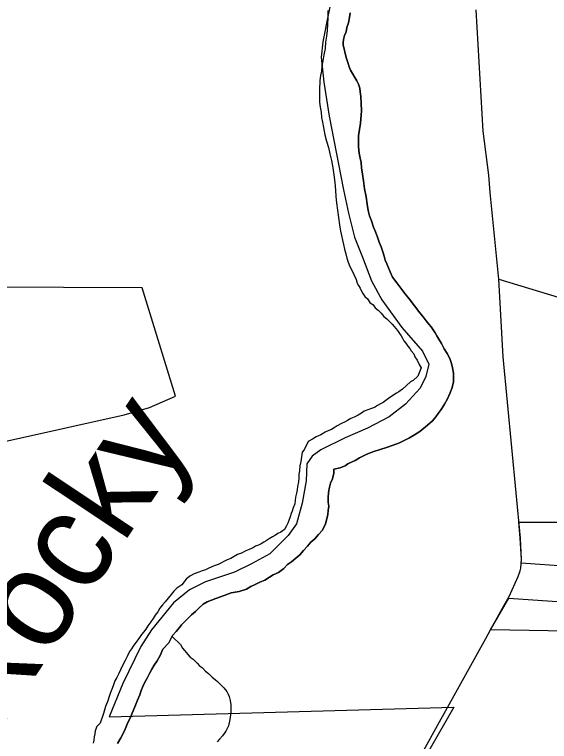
# Model space of a CAD drawing. Extents: x 2010165 to 2382125, y 1060529 to 1407316.
# Drawn here: x 2133800 to 2136008, y 1232184 to 1235186 of the extents above; entities that cross this region are included whole.
import ezdxf

# ---------------------------------------------------------------- set-up
doc = ezdxf.new("R2010")
doc.units = 0
for name, color, linetype in [('GM_X_City_Street', 7, 'Continuous'), ('GM_X_Corporation', 7, 'Continuous'), ('GM_X_County_Road', 7, 'Continuous'), ('GM_X_Major_River', 7, 'Continuous'), ('GM_X_Major_River_Text', 7, 'Continuous'), ('GM_X_Minor_River', 7, 'Continuous')]:
    doc.layers.add(name, color=color, linetype=linetype)

msp = doc.modelspace()

# ---------------------------------------------------------------- linework, layer by layer
at = {"layer": 'GM_X_City_Street'}
msp.add_lwpolyline([(2134256.4, 1229179.8), (2134217.3, 1230093.2), (2134232.4, 1230413.1), (2134251.3, 1230729.2), (2134250, 1230896), (2134276.8, 1231168.9), (2134371.9, 1231445.9), (2134414, 1231531.8), (2134446.8, 1231590.3), (2134486.2, 1231614), (2134514.5, 1231617.7), (2134918.3, 1231605.8), (2135099.6, 1231604.1), (2135244.1, 1231759), (2135312.9, 1231864.6), (2135445.4, 1232068.5), (2135560.9, 1232277.3), (2135566.6, 1232287.6)], dxfattribs=at)
at = {"layer": 'GM_X_Corporation'}
for points in [[(2130665.6, 1232672.5), (2131903.1, 1232704.3), (2131906.6, 1232844.7), (2132365.2, 1232836.8), (2132374.9, 1233391.5), (2133620.9, 1233404.8), (2133665.8, 1233408.5), (2133770.5, 1233426), (2134251.8, 1233533.2), (2134304.2, 1233548.1), (2134356.5, 1233563.1), (2134463.7, 1233610.5), (2134327.1, 1234057.3), (2132374.5, 1234066.3), (2132374.1, 1235700.8)], [(2135154.7, 1235473.1), (2135093.8, 1235177.9), (2135072.1, 1235073.6), (2135066.4, 1235009.3), (2135076.8, 1234907.1), (2135099.4, 1234766.8), (2135158.6, 1234462.3), (2135179, 1234366.1), (2135203.5, 1234265.9), (2135235.8, 1234183.9), (2135274.2, 1234085.8), (2135316.6, 1234007.7), (2135399.2, 1233893.8), (2135483.6, 1233795.9), (2135509.9, 1233741.9), (2135498.1, 1233691.7), (2135474.2, 1233643.5), (2135414.4, 1233577), (2135346.5, 1233524.5), (2135256.6, 1233478), (2135164.6, 1233437.5), (2135064.7, 1233388.9), (2135028.7, 1233362.6), (2135006.8, 1233330.4), (2135003.1, 1233260.2), (2134987.4, 1233167.9), (2134963.7, 1233083.5), (2134929.9, 1233035.3), (2134854.1, 1232958.7), (2134778.1, 1232918.2), (2134708.2, 1232883.8), (2134588.2, 1232843.1), (2134522.2, 1232810.7), (2134456.3, 1232756.3), (2134364.6, 1232645.5), (2134320.8, 1232577.2), (2134247.3, 1232424.4), (2134189.8, 1232285.7), (2135613.5, 1232326.5), (2135412.6, 1231974.5)], [(2136086.2, 1232907.1), (2135891.6, 1232920.2), (2135892.6, 1232935.4), (2135888, 1233024), (2135881.7, 1233090.1), (2136401.5, 1233090.1)], [(2139105.1, 1232587.1), (2135765.5, 1232645.4), (2135840.1, 1232775.5), (2136059.6, 1232760.8)]]:
    msp.add_lwpolyline(points, dxfattribs=at)
at = {"layer": 'GM_X_County_Road'}
for points in [[(2135889.6, 1232994), (2135888.1, 1233024), (2135816.7, 1233771.8), (2135799.8, 1234093.1), (2135763.7, 1234450.9), (2135758.5, 1234522.7), (2135735.2, 1234704.1), (2135705.7, 1235205.1)], [(2135799.8, 1234093.1), (2136211.7, 1233968.5), (2136363.9, 1233924), (2136372.3, 1233921.9)], [(2132404, 1233383.6), (2132621, 1233388.5), (2132832.9, 1233396), (2133473.8, 1233396), (2133576, 1233401), (2133620.9, 1233404.8), (2133665.8, 1233408.5), (2133770.5, 1233425.9), (2134251.8, 1233533.2), (2134304.2, 1233548.2), (2134356.5, 1233563.1), (2134463.7, 1233610.5)], [(2135887.2, 1232889.6), (2135890.3, 1232899.8), (2135892.6, 1232935.4), (2135889.6, 1232994)], [(2135821.9, 1232746.6), (2135841.9, 1232782.4), (2135879.7, 1232864.9), (2135887.2, 1232889.6)], [(2135745.2, 1232609), (2135765.4, 1232645.3), (2135821.9, 1232746.6)], [(2135566.6, 1232287.6), (2135745.2, 1232609)]]:
    msp.add_lwpolyline(points, dxfattribs=at)
at = {"layer": 'GM_X_Major_River'}
for points in [[(2135093.8, 1235202.7), (2135093.9, 1235170.6), (2135092, 1235146.5), (2135090.1, 1235120.4), (2135088.1, 1235096.3), (2135084.2, 1235072.2), (2135082.3, 1235046.1), (2135076.3, 1235020), (2135072.4, 1234993.9), (2135068.5, 1234973.9), (2135066.5, 1234951.8), (2135062.6, 1234933.7), (2135060.7, 1234913.6), (2135060.7, 1234899.6)], [(2135093.8, 1235202.7), (2135093.9, 1235170.6), (2135092, 1235146.5), (2135090.1, 1235120.4), (2135088.1, 1235096.3), (2135084.2, 1235072.2), (2135082.3, 1235046.1), (2135076.3, 1235020), (2135072.4, 1234993.9), (2135068.5, 1234973.9), (2135066.5, 1234951.8), (2135062.6, 1234933.7), (2135060.7, 1234913.6), (2135060.7, 1234899.6)], [(2135186.1, 1235193), (2135182.2, 1235172.9), (2135178.2, 1235150.8), (2135172.3, 1235132.7), (2135168.3, 1235114.6), (2135162.4, 1235098.6), (2135158.4, 1235082.5), (2135156.4, 1235070.4), (2135156.5, 1235060.4), (2135168.7, 1235008.3), (2135172.7, 1234996.3), (2135176.8, 1234984.2), (2135180.9, 1234970.2), (2135186.9, 1234956.2), (2135195, 1234942.1), (2135205.1, 1234926.1), (2135213.2, 1234912.1), (2135219.2, 1234898.1), (2135225.3, 1234882.1), (2135227.4, 1234866), (2135229.4, 1234847.9), (2135231.5, 1234819.9), (2135231.7, 1234787.8), (2135227.8, 1234737.6), (2135223.9, 1234711.5), (2135220, 1234685.4), (2135220.1, 1234661.3), (2135220.1, 1234639.2), (2135222.2, 1234613.1), (2135226.3, 1234593.1), (2135230.4, 1234575.1), (2135232.5, 1234553), (2135236.6, 1234526.9), (2135240.7, 1234498.8), (2135244.8, 1234466.7), (2135250.9, 1234432.6), (2135255.1, 1234402.6), (2135259.2, 1234376.5), (2135265.2, 1234354.4), (2135273.3, 1234334.4), (2135281.5, 1234308.3), (2135289.6, 1234288.3), (2135297.7, 1234266.2), (2135305.8, 1234246.2), (2135313.9, 1234226.1), (2135319.9, 1234206.1), (2135326, 1234188.1), (2135330.1, 1234172), (2135336.2, 1234156), (2135344.2, 1234140), (2135350.3, 1234123.9), (2135360.4, 1234101.9), (2135378.6, 1234077.9), (2135394.7, 1234055.8), (2135410.8, 1234033.8), (2135429, 1234011.8), (2135473.3, 1233953.8), (2135487.4, 1233937.7), (2135499.5, 1233921.7), (2135509.6, 1233907.7), (2135519.7, 1233895.7), (2135527.7, 1233883.7), (2135535.8, 1233871.7), (2135543.9, 1233859.7), (2135551.9, 1233845.6), (2135562, 1233827.6), (2135574.1, 1233805.6), (2135586.3, 1233785.6), (2135596.4, 1233765.5), (2135604.5, 1233745.5), (2135608.5, 1233727.4), (2135612.6, 1233705.4), (2135612.7, 1233683.3), (2135612.7, 1233669.2), (2135608.8, 1233657.2), (2135604.8, 1233641.1), (2135596.9, 1233621), (2135586.9, 1233598.9), (2135574.9, 1233576.8), (2135561, 1233554.7), (2135549, 1233538.6), (2135539, 1233524.5), (2135525, 1233508.4), (2135505, 1233490.3), (2135473, 1233464.1), (2135451, 1233450), (2135430.9, 1233437.9), (2135410.9, 1233427.8), (2135388.9, 1233417.7), (2135362.8, 1233407.6), (2135334.8, 1233397.5), (2135308.7, 1233389.4), (2135282.6, 1233381.3), (2135260.6, 1233373.2), (2135246.6, 1233367.1)], [(2135246.6, 1233367.1), (2135260.6, 1233373.2), (2135282.6, 1233381.3), (2135308.7, 1233389.4), (2135334.8, 1233397.5), (2135362.8, 1233407.6), (2135388.9, 1233417.7), (2135410.9, 1233427.8), (2135430.9, 1233437.9), (2135451, 1233450), (2135473, 1233464.1), (2135505, 1233490.3), (2135525, 1233508.4), (2135539, 1233524.5), (2135549, 1233538.6), (2135561, 1233554.7), (2135574.9, 1233576.8), (2135586.9, 1233598.9), (2135596.9, 1233621), (2135604.8, 1233641.1), (2135608.8, 1233657.2), (2135612.7, 1233669.2), (2135612.7, 1233683.3), (2135612.6, 1233705.4), (2135608.5, 1233727.4), (2135604.5, 1233745.5), (2135596.4, 1233765.5), (2135586.3, 1233785.6), (2135574.1, 1233805.6), (2135562, 1233827.6), (2135551.9, 1233845.6), (2135543.9, 1233859.7), (2135535.8, 1233871.7), (2135527.7, 1233883.7), (2135519.7, 1233895.7), (2135509.6, 1233907.7), (2135499.5, 1233921.7), (2135487.4, 1233937.7), (2135473.3, 1233953.8), (2135429, 1234011.8), (2135410.8, 1234033.8), (2135394.7, 1234055.8), (2135378.6, 1234077.9), (2135360.4, 1234101.9), (2135350.3, 1234123.9), (2135344.2, 1234140), (2135336.2, 1234156), (2135330.1, 1234172), (2135326, 1234188.1), (2135319.9, 1234206.1), (2135313.9, 1234226.1), (2135305.8, 1234246.2), (2135297.7, 1234266.2), (2135289.6, 1234288.3), (2135281.5, 1234308.3), (2135273.3, 1234334.4), (2135265.2, 1234354.4), (2135259.2, 1234376.5), (2135255.1, 1234402.6), (2135250.9, 1234432.6), (2135244.8, 1234466.7), (2135240.7, 1234498.8), (2135236.6, 1234526.9), (2135232.5, 1234553), (2135230.4, 1234575.1), (2135226.3, 1234593.1), (2135222.2, 1234613.1), (2135220.1, 1234639.2), (2135220.1, 1234661.3), (2135220, 1234685.4), (2135223.9, 1234711.5), (2135227.8, 1234737.6), (2135231.7, 1234787.8), (2135231.5, 1234819.9), (2135229.4, 1234847.9), (2135227.4, 1234866), (2135225.3, 1234882.1), (2135219.2, 1234898.1), (2135213.2, 1234912.1), (2135205.1, 1234926.1), (2135195, 1234942.1), (2135186.9, 1234956.2), (2135180.9, 1234970.2), (2135176.8, 1234984.2), (2135172.7, 1234996.3), (2135168.7, 1235008.3), (2135156.5, 1235060.4), (2135156.4, 1235070.4), (2135158.4, 1235082.5), (2135162.4, 1235098.6), (2135168.3, 1235114.6), (2135172.3, 1235132.7), (2135178.2, 1235150.8), (2135182.2, 1235172.9), (2135186.1, 1235193)], [(2135060.7, 1234899.6), (2135058.7, 1234887.5), (2135058.8, 1234873.5), (2135058.8, 1234859.4), (2135058.9, 1234843.4), (2135059, 1234823.3), (2135061, 1234803.3), (2135065.1, 1234783.2), (2135067.2, 1234761.1), (2135071.3, 1234741.1), (2135075.4, 1234719), (2135081.5, 1234688.9), (2135087.6, 1234662.9), (2135095.7, 1234636.8), (2135101.8, 1234610.8), (2135107.9, 1234582.7), (2135114.1, 1234552.6), (2135118.2, 1234524.5), (2135122.3, 1234492.4), (2135124.4, 1234460.3), (2135126.5, 1234434.2), (2135128.6, 1234408.2), (2135132.7, 1234378.1), (2135136.9, 1234348), (2135141, 1234317.9), (2135145.1, 1234291.8), (2135149.1, 1234273.8), (2135153.2, 1234253.7), (2135157.3, 1234235.7), (2135161.4, 1234217.6), (2135167.5, 1234197.6), (2135171.5, 1234179.6), (2135177.6, 1234163.5), (2135183.7, 1234145.5), (2135193.8, 1234127.4), (2135210, 1234091.4), (2135214, 1234077.3), (2135220.1, 1234067.3), (2135226.1, 1234055.3), (2135232.2, 1234043.3), (2135238.3, 1234033.3), (2135246.3, 1234021.3), (2135256.4, 1234011.3), (2135266.5, 1233997.2), (2135280.6, 1233987.2), (2135288.6, 1233975.2), (2135300.7, 1233965.2), (2135312.8, 1233953.2), (2135324.9, 1233939.2), (2135336.9, 1233929.2), (2135349, 1233917.2), (2135359.1, 1233907.2), (2135367.2, 1233897.2), (2135381.3, 1233881.2), (2135389.3, 1233869.2), (2135395.4, 1233859.2), (2135401.4, 1233849.2), (2135407.5, 1233839.2), (2135415.5, 1233829.2), (2135423.6, 1233817.1), (2135431.7, 1233807.1), (2135437.7, 1233797.1), (2135447.8, 1233785.1), (2135451.9, 1233773.1), (2135461.9, 1233759.1), (2135470, 1233741), (2135478.1, 1233727), (2135464.2, 1233692.9), (2135446.2, 1233674.7), (2135434.2, 1233668.7), (2135402.2, 1233638.5), (2135386.1, 1233628.4), (2135376.1, 1233622.3), (2135362.1, 1233612.3), (2135344.1, 1233600.2), (2135332.1, 1233592.1), (2135322.1, 1233584.1), (2135310.1, 1233578), (2135298, 1233571.9), (2135286, 1233563.9), (2135274, 1233559.8), (2135258, 1233553.8), (2135243.9, 1233547.7), (2135231.9, 1233539.6), (2135217.9, 1233531.6), (2135201.9, 1233523.5), (2135187.9, 1233517.4), (2135173.8, 1233509.3), (2135161.8, 1233503.3), (2135149.8, 1233497.2), (2135131.8, 1233487.1), (2135119.8, 1233479.1), (2135107.8, 1233473), (2135097.7, 1233469), (2135081.7, 1233460.9), (2135063.7, 1233450.8), (2135045.6, 1233442.7), (2135029.6, 1233432.6), (2135011.6, 1233422.5), (2134995.7, 1233388.4), (2134987.7, 1233378.3)], [(2135060.7, 1234899.6), (2135058.7, 1234887.5), (2135058.8, 1234873.5), (2135058.8, 1234859.4), (2135058.9, 1234843.4), (2135059, 1234823.3), (2135061, 1234803.3), (2135065.1, 1234783.2), (2135067.2, 1234761.1), (2135071.3, 1234741.1), (2135075.4, 1234719), (2135081.5, 1234688.9), (2135087.6, 1234662.9), (2135095.7, 1234636.8), (2135101.8, 1234610.8), (2135107.9, 1234582.7), (2135114.1, 1234552.6), (2135118.2, 1234524.5), (2135122.3, 1234492.4), (2135124.4, 1234460.3), (2135126.5, 1234434.2), (2135128.6, 1234408.2), (2135132.7, 1234378.1), (2135136.9, 1234348), (2135141, 1234317.9), (2135145.1, 1234291.8), (2135149.1, 1234273.8), (2135153.2, 1234253.7), (2135157.3, 1234235.7), (2135161.4, 1234217.6), (2135167.5, 1234197.6), (2135171.5, 1234179.6), (2135177.6, 1234163.5), (2135183.7, 1234145.5), (2135193.8, 1234127.4), (2135210, 1234091.4), (2135214, 1234077.3), (2135220.1, 1234067.3), (2135226.1, 1234055.3), (2135232.2, 1234043.3), (2135238.3, 1234033.3), (2135246.3, 1234021.3), (2135256.4, 1234011.3), (2135266.5, 1233997.2), (2135280.6, 1233987.2), (2135288.6, 1233975.2), (2135300.7, 1233965.2), (2135312.8, 1233953.2), (2135324.9, 1233939.2), (2135336.9, 1233929.2), (2135349, 1233917.2), (2135359.1, 1233907.2), (2135367.2, 1233897.2), (2135381.3, 1233881.2), (2135389.3, 1233869.2), (2135395.4, 1233859.2), (2135401.4, 1233849.2), (2135407.5, 1233839.2), (2135415.5, 1233829.2), (2135423.6, 1233817.1), (2135431.7, 1233807.1), (2135437.7, 1233797.1), (2135447.8, 1233785.1), (2135451.9, 1233773.1), (2135461.9, 1233759.1), (2135470, 1233741), (2135478.1, 1233727), (2135464.2, 1233692.9), (2135446.2, 1233674.7), (2135434.2, 1233668.7), (2135402.2, 1233638.5), (2135386.1, 1233628.4), (2135376.1, 1233622.3), (2135362.1, 1233612.3), (2135344.1, 1233600.2), (2135332.1, 1233592.1), (2135322.1, 1233584.1), (2135310.1, 1233578), (2135298, 1233571.9), (2135286, 1233563.9), (2135274, 1233559.8), (2135258, 1233553.8), (2135243.9, 1233547.7), (2135231.9, 1233539.6), (2135217.9, 1233531.6), (2135201.9, 1233523.5), (2135187.9, 1233517.4), (2135173.8, 1233509.3), (2135161.8, 1233503.3), (2135149.8, 1233497.2), (2135131.8, 1233487.1), (2135119.8, 1233479.1), (2135107.8, 1233473), (2135097.7, 1233469), (2135081.7, 1233460.9), (2135063.7, 1233450.8), (2135045.6, 1233442.7), (2135029.6, 1233432.6), (2135011.6, 1233422.5), (2134995.7, 1233388.4), (2134987.7, 1233378.3)], [(2134987.7, 1233378.3), (2134981.8, 1233340.2), (2134977.8, 1233322.1), (2134975.9, 1233302), (2134973.9, 1233288), (2134974, 1233271.9), (2134972, 1233255.9), (2134968.1, 1233237.8), (2134966.1, 1233223.7), (2134964.2, 1233209.7), (2134960.2, 1233193.6), (2134956.3, 1233165.5), (2134950.3, 1233149.4), (2134946.4, 1233135.4), (2134942.4, 1233125.3), (2134938.4, 1233111.3), (2134932.5, 1233097.2), (2134928.5, 1233085.2), (2134922.5, 1233075.1), (2134914.5, 1233059), (2134898.5, 1233048.9), (2134886.5, 1233042.9), (2134876.5, 1233036.8), (2134864.5, 1233028.8), (2134850.4, 1233020.7), (2134838.4, 1233012.6), (2134828.4, 1233006.6), (2134818.4, 1233000.5), (2134806.4, 1232994.5), (2134794.4, 1232990.4), (2134782.4, 1232982.4), (2134764.3, 1232976.3), (2134752.3, 1232970.2), (2134736.3, 1232962.1), (2134720.2, 1232956.1), (2134706.2, 1232948), (2134692.2, 1232939.9), (2134678.2, 1232933.9), (2134640.1, 1232915.7), (2134624.1, 1232909.6), (2134602, 1232899.5), (2134588, 1232893.4), (2134574, 1232889.4), (2134560, 1232883.3), (2134541.9, 1232877.2), (2134523.9, 1232867.2), (2134507.9, 1232855.1), (2134489.9, 1232830.9), (2134469.9, 1232816.8), (2134457.9, 1232804.8), (2134445.9, 1232790.7), (2134433.9, 1232776.6), (2134421.9, 1232760.5), (2134409.9, 1232748.4), (2134399.9, 1232734.3), (2134392, 1232720.3), (2134380, 1232706.2), (2134372, 1232692.1), (2134362, 1232678), (2134350, 1232661.9), (2134342, 1232647.9), (2134332.1, 1232635.8), (2134324.1, 1232625.7), (2134316.1, 1232613.7), (2134308.1, 1232603.6), (2134300.1, 1232593.6), (2134290.1, 1232577.5), (2134282.1, 1232567.4), (2134274.1, 1232555.3), (2134266.2, 1232537.3), (2134256.2, 1232519.2), (2134248.2, 1232503.1), (2134238.3, 1232483), (2134230.3, 1232464.9), (2134222.3, 1232448.8), (2134214.4, 1232434.8), (2134208.4, 1232418.7), (2134202.4, 1232402.6), (2134196.5, 1232386.5), (2134190.5, 1232370.5), (2134184.5, 1232352.4), (2134174.6, 1232328.3), (2134166.7, 1232300.2), (2134152.7, 1232260), (2134138.8, 1232245.9), (2134132.8, 1232227.8), (2134130.8, 1232215.8), (2134128.9, 1232203.7), (2134126.9, 1232189.7), (2134124.9, 1232177.6)], [(2134987.7, 1233378.3), (2134981.8, 1233340.2), (2134977.8, 1233322.1), (2134975.9, 1233302), (2134973.9, 1233288), (2134974, 1233271.9), (2134972, 1233255.9), (2134968.1, 1233237.8), (2134966.1, 1233223.7), (2134964.2, 1233209.7), (2134960.2, 1233193.6), (2134956.3, 1233165.5), (2134950.3, 1233149.4), (2134946.4, 1233135.4), (2134942.4, 1233125.3), (2134938.4, 1233111.3), (2134932.5, 1233097.2), (2134928.5, 1233085.2), (2134922.5, 1233075.1), (2134914.5, 1233059), (2134898.5, 1233048.9), (2134886.5, 1233042.9), (2134876.5, 1233036.8), (2134864.5, 1233028.8), (2134850.4, 1233020.7), (2134838.4, 1233012.6), (2134828.4, 1233006.6), (2134818.4, 1233000.5), (2134806.4, 1232994.5), (2134794.4, 1232990.4), (2134782.4, 1232982.4), (2134764.3, 1232976.3), (2134752.3, 1232970.2), (2134736.3, 1232962.1), (2134720.2, 1232956.1), (2134706.2, 1232948), (2134692.2, 1232939.9), (2134678.2, 1232933.9), (2134640.1, 1232915.7), (2134624.1, 1232909.6), (2134602, 1232899.5), (2134588, 1232893.4), (2134574, 1232889.4), (2134560, 1232883.3), (2134541.9, 1232877.2), (2134523.9, 1232867.2), (2134507.9, 1232855.1), (2134489.9, 1232830.9), (2134469.9, 1232816.8), (2134457.9, 1232804.8), (2134445.9, 1232790.7), (2134433.9, 1232776.6), (2134421.9, 1232760.5), (2134409.9, 1232748.4), (2134399.9, 1232734.3), (2134392, 1232720.3), (2134380, 1232706.2), (2134372, 1232692.1), (2134362, 1232678), (2134350, 1232661.9), (2134342, 1232647.9), (2134332.1, 1232635.8), (2134324.1, 1232625.7), (2134316.1, 1232613.7), (2134308.1, 1232603.6), (2134300.1, 1232593.6), (2134290.1, 1232577.5), (2134282.1, 1232567.4), (2134274.1, 1232555.3), (2134266.2, 1232537.3), (2134256.2, 1232519.2), (2134248.2, 1232503.1), (2134238.3, 1232483), (2134230.3, 1232464.9), (2134222.3, 1232448.8), (2134214.4, 1232434.8), (2134208.4, 1232418.7), (2134202.4, 1232402.6), (2134196.5, 1232386.5), (2134190.5, 1232370.5), (2134184.5, 1232352.4), (2134174.6, 1232328.3), (2134166.7, 1232300.2), (2134152.7, 1232260), (2134138.8, 1232245.9), (2134132.8, 1232227.8), (2134130.8, 1232215.8), (2134128.9, 1232203.7), (2134126.9, 1232189.7), (2134124.9, 1232177.6)], [(2135246.6, 1233367.1), (2135224.5, 1233355), (2135206.5, 1233344.9), (2135196.5, 1233340.8), (2135176.5, 1233330.8), (2135164.4, 1233322.7), (2135154.4, 1233318.6), (2135144.4, 1233314.6), (2135118.3, 1233308.5), (2135118.4, 1233292.4), (2135112.5, 1233268.3), (2135104.5, 1233250.3), (2135100.5, 1233234.2), (2135096.6, 1233212.1), (2135094.7, 1233190), (2135094.7, 1233172), (2135096.8, 1233155.9), (2135094.9, 1233137.9), (2135092.9, 1233121.8), (2135089, 1233103.7), (2135083, 1233083.6), (2135071.1, 1233057.5), (2135055.1, 1233039.4), (2135039.1, 1233021.3), (2135023.1, 1233007.2), (2135009.1, 1232991.1), (2134993.1, 1232973), (2134977.1, 1232954.9), (2134961.1, 1232940.8), (2134943.1, 1232926.7), (2134927.1, 1232914.6), (2134911.1, 1232898.5), (2134889.1, 1232882.4), (2134867, 1232872.3), (2134853, 1232862.2), (2134833, 1232850.1), (2134812.9, 1232842), (2134792.9, 1232831.9), (2134774.9, 1232823.8), (2134756.8, 1232813.7), (2134726.8, 1232803.6), (2134694.7, 1232797.5), (2134664.6, 1232787.3), (2134630.6, 1232775.2), (2134594.5, 1232761), (2134578.5, 1232750.9), (2134562.5, 1232736.8), (2134546.5, 1232720.8), (2134530.5, 1232706.6), (2134488.5, 1232666.4), (2134480.5, 1232654.3), (2134466.5, 1232638.2), (2134452.5, 1232622.1), (2134436.5, 1232592), (2134412.6, 1232565.8), (2134400.6, 1232539.7), (2134388.6, 1232517.6), (2134376.7, 1232499.5), (2134366.7, 1232483.4), (2134356.7, 1232465.3), (2134346.8, 1232445.2), (2134336.8, 1232427.1), (2134328.8, 1232411), (2134322.8, 1232395), (2134316.9, 1232376.9), (2134306.9, 1232354.8), (2134299, 1232334.7), (2134289, 1232310.6), (2134279.1, 1232284.5), (2134265.1, 1232256.3), (2134253.2, 1232228.2), (2134239.2, 1232200.1), (2134225.3, 1232175.9)], [(2134225.3, 1232175.9), (2134239.2, 1232200.1), (2134253.2, 1232228.2), (2134265.1, 1232256.3), (2134279.1, 1232284.5), (2134289, 1232310.6), (2134299, 1232334.7), (2134306.9, 1232354.8), (2134316.9, 1232376.9), (2134322.8, 1232395), (2134328.8, 1232411), (2134336.8, 1232427.1), (2134346.8, 1232445.2), (2134356.7, 1232465.3), (2134366.7, 1232483.4), (2134376.7, 1232499.5), (2134388.6, 1232517.6), (2134400.6, 1232539.7), (2134412.6, 1232565.8), (2134436.5, 1232592), (2134452.5, 1232622.1), (2134466.5, 1232638.2), (2134480.5, 1232654.3), (2134488.5, 1232666.4), (2134530.5, 1232706.6), (2134546.5, 1232720.8), (2134562.5, 1232736.8), (2134578.5, 1232750.9), (2134594.5, 1232761), (2134630.6, 1232775.2), (2134664.6, 1232787.3), (2134694.7, 1232797.5), (2134726.8, 1232803.6), (2134756.8, 1232813.7), (2134774.9, 1232823.8), (2134792.9, 1232831.9), (2134812.9, 1232842), (2134833, 1232850.1), (2134853, 1232862.2), (2134867, 1232872.3), (2134889.1, 1232882.4), (2134911.1, 1232898.5), (2134927.1, 1232914.6), (2134943.1, 1232926.7), (2134961.1, 1232940.8), (2134977.1, 1232954.9), (2134993.1, 1232973), (2135009.1, 1232991.1), (2135023.1, 1233007.2), (2135039.1, 1233021.3), (2135055.1, 1233039.4), (2135071.1, 1233057.5), (2135083, 1233083.6), (2135089, 1233103.7), (2135092.9, 1233121.8), (2135094.9, 1233137.9), (2135096.8, 1233155.9), (2135094.7, 1233172), (2135094.7, 1233190), (2135096.6, 1233212.1), (2135100.5, 1233234.2), (2135104.5, 1233250.3), (2135112.5, 1233268.3), (2135118.4, 1233292.4), (2135118.3, 1233308.5), (2135144.4, 1233314.6), (2135154.4, 1233318.6), (2135164.4, 1233322.7), (2135176.5, 1233330.8), (2135196.5, 1233340.8), (2135206.5, 1233344.9), (2135224.5, 1233355), (2135246.6, 1233367.1)]]:
    msp.add_lwpolyline(points, dxfattribs=at)
at = {"layer": 'GM_X_Minor_River'}
msp.add_lwpolyline([(2134449.9, 1232617.3), (2134484.7, 1232584.1), (2134492.8, 1232570.1), (2134500.9, 1232560.1), (2134517, 1232542.1), (2134525.1, 1232532.1), (2134537.1, 1232524.1), (2134553.2, 1232508.1), (2134563.3, 1232496.1), (2134575.4, 1232488.1), (2134587.4, 1232476.1), (2134601.5, 1232464.1), (2134615.6, 1232450.1), (2134627.7, 1232440.1), (2134637.8, 1232432.1), (2134647.8, 1232422.1), (2134663.9, 1232406.1), (2134676, 1232390.1), (2134682.1, 1232380.1), (2134686.1, 1232370), (2134690.2, 1232354), (2134692.3, 1232335.9), (2134692.4, 1232303.8), (2134688.5, 1232275.7), (2134682.5, 1232249.6), (2134672.6, 1232227.5), (2134658.6, 1232207.4), (2134646.6, 1232193.3), (2134636.6, 1232183.2)], dxfattribs=at)

# ---------------------------------------------------------------- texts
at = {"layer": 'GM_X_Major_River_Text'}
msp.add_text('Rocky', height=400.24, rotation=56.3799, dxfattribs=at).set_placement((2133718.9, 1232202.3))

doc.saveas('drawing.dxf')
